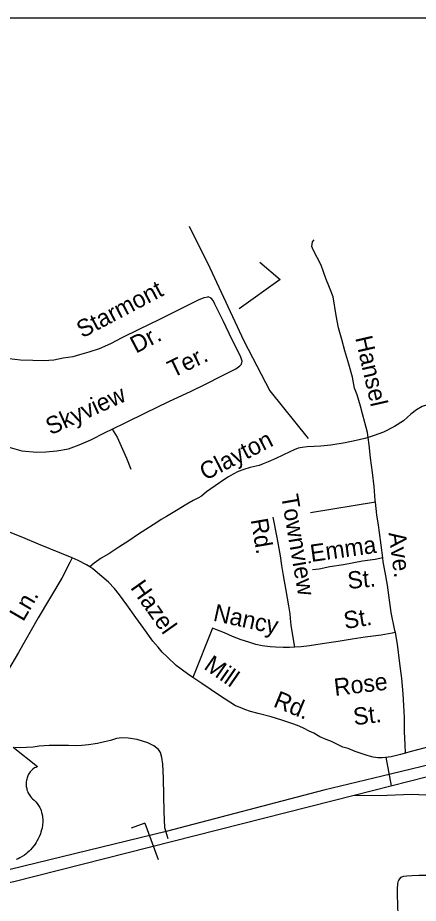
# Model space of a CAD drawing. Extents: x 925297 to 940193, y 663541 to 689899.
# Drawn here: x 928734 to 929084, y 688730 to 689501 of the extents above; entities that cross this region are included whole.
import ezdxf

# ---------------------------------------------------------------- set-up
doc = ezdxf.new("R2010")
doc.units = 0
doc.layers.add('Default', color=7, linetype='Continuous')
doc.layers.add('Sheet Title CELL', color=7, linetype='Continuous')

msp = doc.modelspace()

# ---------------------------------------------------------------- linework, layer by layer
at = {"layer": 'Default'}
for p, q in [((929046.25, 689079.6), (928989.58, 689070.13)), ((929055.14, 688857.27), (929059.94, 688832.44)), ((928845.3, 688799.86), (928833.38, 688795.53)), ((928845.3, 688799.86), (928856.82, 688768.17))]:
    msp.add_line(p, q, dxfattribs=at)
for points in [[(928883.88, 689319.79), (928901.86, 689283.46), (928931.5, 689219.86), (928954.13, 689176.36), (928987.7, 689134.99)], [(929039.9, 689135.71), (929039.24, 689140.05), (929037.1, 689148.95), (929034.96, 689156.5), (929033.15, 689163.15), (929030.23, 689172.83), (929027.86, 689178.81), (929026.17, 689188.38), (929022.9, 689199.76), (929019.52, 689211.36), (929016.93, 689221.16), (929013.89, 689231.19), (929012.09, 689242), (929009.38, 689258.34), (929006.11, 689266.33), (929003.07, 689274.33), (928998.79, 689285.71), (928991.92, 689299.12), (928990.68, 689302.16), (928991.36, 689306.1), (928992.71, 689308.02)], [(928945.31, 689288.51), (928963.09, 689273.26), (928927.54, 689247.85)], [(928722.08, 689205.21), (928736.64, 689203.34), (928747.49, 689203.04), (928757.24, 689202.93), (928765.86, 689203.55), (928773.89, 689205.03), (928782.74, 689206.42), (928788.63, 689208.03), (928796.74, 689210.47), (928805.76, 689213.42), (928815.49, 689217.56), (928825.3, 689222.87), (928840.17, 689229.99), (928858.28, 689238.96), (928876.15, 689247.69), (928891.9, 689255.72), (928896.9, 689257.8), (928900.17, 689258.3)], [(928929.37, 689199.72), (928929.91, 689202.27), (928928.49, 689206.6), (928921.03, 689221.35), (928913.89, 689236.75), (928906.24, 689251.91), (928904.72, 689255.21), (928902.99, 689257.12), (928900.43, 689258.34), (928900.17, 689258.3)], [(928816.56, 689142.99), (928828.52, 689148.76), (928845.66, 689157.13), (928865.97, 689167.06), (928885.44, 689176.24), (928897.98, 689182.32), (928912.34, 689189.51), (928924.55, 689195.56), (928927.99, 689198.06), (928929.35, 689199.59), (928929.37, 689199.72)], [(929091.59, 689164.22), (929086.94, 689162.68), (929082.03, 689159.98), (929076.97, 689156.13), (929070.78, 689150.36), (929062.73, 689145.3), (929053.32, 689140.42), (929045.08, 689137.59), (929039.9, 689135.71)], [(928717.98, 689130.56), (928725.72, 689127.72), (928738.02, 689124.19), (928751.1, 689123.08), (928758.87, 689123.16), (928768.57, 689124.19), (928778.5, 689125.92), (928787.98, 689129.35), (928798.15, 689133.88), (928810.55, 689140.09), (928816.56, 689142.99)], [(928816.56, 689142.99), (928820.96, 689136.05), (928829.33, 689117.68), (928832.95, 689108.14)], [(929039.9, 689135.71), (929036.99, 689134.83), (929029.46, 689133.2), (929019.87, 689131.05), (929007.35, 689129.03), (928998.56, 689128.19), (928992.93, 689127.81), (928986.72, 689127.62), (928982.47, 689127.21), (928978.96, 689126.48), (928975.49, 689125.15), (928971.57, 689123.38), (928965.46, 689120.53), (928959.4, 689117.5), (928952.62, 689114.64), (928948.27, 689112.75), (928944.94, 689111.44), (928942.23, 689110.79), (928937.06, 689109.72), (928931.39, 689107.89), (928926.58, 689106.08), (928922.1, 689103.76), (928918.15, 689101.52), (928914.81, 689099.39), (928906.47, 689093.55), (928899.02, 689088.57), (928894.46, 689084.8), (928891.31, 689083.01), (928887.19, 689080.96), (928881.68, 689077.71), (928872.75, 689072.18), (928864.16, 689066.9), (928859.46, 689064.38), (928855.54, 689061.89), (928849.1, 689057.83), (928839.77, 689051.57), (928831.1, 689045.84), (928822.5, 689040.31), (928813.65, 689034.45), (928807.19, 689030.69), (928801.13, 689026.36), (928797.1, 689023.13)], [(929046.25, 689079.6), (929046.09, 689080.92), (929044.98, 689093.25), (929043.58, 689105.23), (929041.9, 689118.01), (929040.71, 689129.51), (929039.9, 689135.71)], [(929052.65, 689030.94), (929049.79, 689053.02), (929048.81, 689059.31), (929047.58, 689068.57), (929046.25, 689079.6)], [(928781.78, 689030.89), (928772.58, 689034.71), (928752.53, 689042.9), (928738.88, 689048.57), (928724.95, 689054.2), (928709.93, 689060.53), (928695.5, 689066.7), (928691.32, 689068.56)], [(928975.81, 688953.19), (928975.28, 688956.34), (928972.82, 688972.31), (928972.24, 688978.21), (928971.78, 688982.09), (928970.8, 688989.28), (928968.45, 689002.43), (928965.98, 689015.49), (928964.63, 689024.27), (928963.38, 689032.63), (928960.43, 689048.71), (928956.92, 689066.42)], [(928781.78, 689030.89), (928779.83, 689026.93), (928772.94, 689013.2), (928752.24, 688978.84), (928734.93, 688948.53), (928715.5, 688916.16), (928710.79, 688908.8), (928704.29, 688897.35)], [(928797.1, 689023.13), (928794.21, 689025), (928787.15, 689028.66), (928781.78, 689030.89)], [(929052.65, 689030.94), (929045.97, 689029.47), (929035.04, 689027.97), (929018.32, 689024.93), (929006.6, 689023.1), (928997.25, 689021.25), (928991.29, 689020.61)], [(929063.62, 688965.83), (929063.27, 688967.75), (929059.99, 688983.51), (929057.96, 688998.55), (929056.8, 689007.21), (929054.81, 689018.44), (929053.1, 689027.41), (929052.65, 689030.94)], [(928887.09, 688926.9), (928882.46, 688930.01), (928872.59, 688937.12), (928864.6, 688944.65), (928860.37, 688948.78), (928856.7, 688953.14), (928852.29, 688958.45), (928844.29, 688969.41), (928837.23, 688979.09), (928829.56, 688990.01), (928823.19, 688998.83), (928818.83, 689004.23), (928813.55, 689009.72), (928807.68, 689014.88), (928799.91, 689021.3), (928797.1, 689023.13)], [(928907, 688968.65), (928904.26, 688969.7), (928887.09, 688926.9)], [(928975.81, 688953.19), (928975.42, 688953.16), (928971.31, 688952.98), (928965.84, 688952.99), (928959.04, 688953.19), (928954.3, 688953.53), (928947.61, 688954.36), (928941.8, 688955.64), (928935.88, 688957.49), (928929.05, 688959.69), (928921.47, 688962.53), (928914.72, 688965.57), (928907, 688968.65)], [(929063.62, 688965.83), (929060.75, 688965.28), (929051.28, 688963.77), (929037.16, 688961.89), (929025.86, 688960.1), (929013.61, 688958.22), (928999.9, 688956.14), (928988.84, 688954.35), (928981.34, 688953.62), (928975.81, 688953.19)], [(929072.45, 688860.92), (929072.22, 688868.43), (929071.62, 688879.49), (929071.52, 688891.85), (929070.97, 688902.38), (929070.47, 688912.6), (929069.19, 688925.96), (929067.42, 688938.99), (929065.44, 688955.88), (929063.62, 688965.83)], [(929072.45, 688860.92), (929068.01, 688859.68), (929059.94, 688857.66), (929052.43, 688856.91), (929048.23, 688856.95), (929044.3, 688857.55), (929041.07, 688858.38), (929039.07, 688858.97), (929028.69, 688862.48), (929022.33, 688865.01), (929017.86, 688866.19), (929012.44, 688868.7), (929007.82, 688870.98), (929003.38, 688872.92), (928997.76, 688875.24), (928992.4, 688878.19), (928988.44, 688880.12), (928984, 688882.29), (928979.72, 688884.36), (928975.16, 688886.04), (928969.88, 688887.82), (928964.48, 688889.75), (928955.38, 688892.51), (928943.89, 688895.29), (928937.39, 688897.09), (928932.29, 688898.97), (928928.18, 688900.56), (928924.36, 688902.23), (928919.2, 688905.21), (928911.2, 688910.52), (928894.93, 688921.64), (928887.09, 688926.9)], [(929027.74, 688824.35), (929091.51, 688840.54), (929262.95, 688883.29)], [(929190.42, 688875.58), (929149.29, 688864.98), (929112.36, 688855.44), (929052.19, 688840.84), (929001.1, 688828.77), (928863.79, 688792.71), (928727.82, 688759.49), (928686.82, 688753.06), (928655.56, 688749.51), (928625.66, 688747.58), (928584.13, 688746.27), (928553.43, 688746.59)], [(928865.47, 688786.32), (928862.57, 688795.79), (928861.93, 688810.04), (928861.64, 688823.8), (928861.52, 688839.12), (928860.82, 688851.29), (928859.88, 688857.09), (928858.82, 688861.38), (928857.2, 688864.01), (928853.15, 688867.16), (928847.91, 688869.75), (928838.48, 688872.66), (928830.71, 688873.88), (928825.06, 688874.34), (928820.47, 688873.67), (928815.14, 688872.05), (928809.94, 688870.84), (928804.04, 688869.18), (928796.17, 688868.02), (928790.18, 688867.59), (928785.27, 688867.38), (928778.72, 688867.61), (928774.71, 688867.54), (928768.44, 688867.61), (928761.85, 688867.43), (928753.11, 688866.86), (928747.86, 688866.23), (928742.11, 688865.69), (928736.25, 688865.41), (928731.95, 688865.82)], [(928730.42, 688866.22), (928751.68, 688849.28), (928751.18, 688849.09), (928750.02, 688848.53), (928749.11, 688847.99), (928747.64, 688846.96), (928747.02, 688846.39), (928746.39, 688845.8), (928745.81, 688845.17), (928745.3, 688844.58), (928744.69, 688843.73), (928744.14, 688842.88), (928743.6, 688841.93), (928743.2, 688841.12), (928742.55, 688839.41), (928742.23, 688838.33), (928742.03, 688837.41), (928741.78, 688835.52), (928741.72, 688834.61), (928741.72, 688833.72), (928741.77, 688832.78), (928741.86, 688831.87), (928742.02, 688830.93), (928742.17, 688830.1), (928742.43, 688829.09), (928742.81, 688827.9), (928743.27, 688826.76), (928744.25, 688824.92), (928745.5, 688823.03), (928746.39, 688821.98), (928747.27, 688821.07), (928748.58, 688819.97), (928749.29, 688819.34), (928750.1, 688818.52), (928751.43, 688816.98), (928751.97, 688816.25), (928752.52, 688815.43), (928753.02, 688814.59), (928753.52, 688813.69), (928753.93, 688812.9), (928754.67, 688811.07), (928755.22, 688809.3), (928755.47, 688808.37), (928755.87, 688806.29), (928756.02, 688805.26), (928756.18, 688803.22), (928756.19, 688800.76), (928756, 688798.43), (928755.56, 688795.7), (928755.19, 688794.07), (928754.64, 688792.17), (928754.1, 688790.53), (928753.12, 688788.1), (928752.26, 688786.34), (928751.15, 688784.28), (928750.38, 688783.04), (928749.49, 688781.71), (928748.37, 688780.18), (928747.07, 688778.54), (928745.5, 688776.82), (928744.23, 688775.56), (928742.57, 688774.07), (928741.57, 688773.24), (928740.14, 688772.16), (928738.18, 688770.86), (928736.25, 688769.74), (928734.6, 688768.9), (928733.14, 688768.27)], [(929114.22, 688851.67), (929110.87, 688859.75), (929108.23, 688863.64), (929104.25, 688866.47), (929098.22, 688867.29), (929089.64, 688865.56), (929082.78, 688863.79), (929076.09, 688861.93), (929072.45, 688860.92)], [(928553.42, 688736.09), (928582.01, 688734.9), (928640.54, 688736.24), (928695.65, 688742.2), (928731.09, 688749.06), (929027.74, 688824.35)], [(929027.74, 688824.35), (929049.36, 688824.03), (929077.63, 688825.22), (929096.68, 688824.32), (929119.59, 688819.56)], [(929067.48, 688660.24), (929066.83, 688673.17), (929066.61, 688697.45), (929065.93, 688719.98), (929065.44, 688737.47), (929065.4, 688742.58), (929065.6, 688747.42), (929066.4, 688749.72)], [(929108.94, 688663.7), (929111.3, 688666.43), (929112.62, 688671.03), (929112.14, 688679.96), (929112.31, 688697.45), (929112.37, 688710.68), (929112.61, 688722.6), (929112.33, 688733.46), (929111.33, 688742.29), (929109.75, 688747.64), (929106.64, 688751.17), (929103.33, 688752.74), (929096.45, 688754.02), (929090.6, 688754.27), (929084.08, 688754.39), (929078.13, 688754.15), (929073.55, 688753.81), (929070.57, 688753.47), (929068.16, 688752.56), (929066.69, 688750.55), (929066.4, 688749.72)]]:
    msp.add_lwpolyline(points, dxfattribs=at)
at = {"layer": 'Sheet Title CELL'}
msp.add_lwpolyline([(927148.43, 689501.34), (930192.06, 689501.34), (930192.06, 687400.3), (927148.43, 687400.3)], close=True, dxfattribs=at)

# ---------------------------------------------------------------- texts
at = {"layer": 'Default'}
for s, rotation, p in [('Starmont', 27.7829, (928790.64, 689222.01)), ('Dr.', 27.7829, (928837.44, 689208.64)), ('Hansel', 282.91781, (929028.5, 689222.59)), ('Ter.', 25.65474, (928869.53, 689187.53)), ('Skyview', 24.4532, (928763.01, 689137.61)), ('Clayton', 27.2383, (928897.84, 689097.99)), ('Townview', 279.76508, (928963.89, 689085.07)), ('Rd.', 279.76508, (928937.39, 689064.13)), ('Ave.', 277.42269, (929057.58, 689052.73)), ('Emma', 7.9572, (928990.35, 689027.38)), ('St.', 5.50993, (929022.53, 689003.83)), ('Hazel', 305.26371, (928832.08, 689005.02)), ('Ln.', 59.72093, (928739.12, 688974.83)), ('Nancy', 347.66334, (928904.06, 688976.37)), ('St.', 8.94873, (929019.74, 688968.94)), ('Mill', 325.19329, (928895.76, 688934.81)), ('Rose', 6.79042, (929010.97, 688910.73)), ('Rd.', 337.60248, (928956.38, 688901.75)), ('St.', 6.79042, (929027.73, 688885.15))]:
    msp.add_text(s, height=15, rotation=rotation, dxfattribs=at).set_placement(p)

doc.saveas('drawing.dxf')
